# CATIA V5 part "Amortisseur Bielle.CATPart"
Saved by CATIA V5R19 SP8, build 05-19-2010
Part number: Amortisseur Bielle
Bounding box of the stored display mesh (mm): x -7.5 to 57.5, y -30 to 285, z -32.322 to 32.322
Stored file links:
  C:\Users\ThinkMotion\Desktop\EU_thinkMotion\iao\IAO_MMS_Groupe3\yschmidt\Train1434_yschmidt\Train1434_yschmidt\Amortisseur Bielle.CATPart
  C:\Users\ThinkMotion\Desktop\EU_thinkMotion\iao\IAO_MMS_Groupe3\yschmidt\Train1434_yschmidt\Train1434_yschmidt\AssemblageTrainOptimise.CATProduct
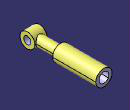
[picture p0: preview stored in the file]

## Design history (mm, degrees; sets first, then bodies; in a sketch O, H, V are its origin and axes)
Set1
  Line1: linked copy from another document
  Plane1: linked copy from another document
Body1 (main body)
  Sketch1 on yz-plane, origin (0, 0, 0), H (0, 1, 0), V (0, 0, 1)
    circle A1 centre (0, 0) radius 30
    reference projected point E1 (0, 0) from Line1
    radius A1 = 30
    concentricity: E1 A1
  Pad1: profile Sketch1, direction (1, 0, 0), length 50
  Sketch2 on zx-plane, origin (0, 0, 0), H (-1, 0, 0), V (0, 0, 1)
    circle A1 centre (-25, 0) radius 20
    point P1 (-25, 0)
    reference projected line E1 (0, -30) -> (0, 30) from edge [start face of Pad1 | face of Pad1 from Sketch1.A1]
    radius A1 = 20
    distance P1 E1 = 25
    coincidence: P1 H
  Pad2: profile Sketch2, direction (0, 1, 0), length 110
  Sketch3 on end face of Pad1, origin (50, 0, 0), H (0, 1, 0), V (0, 0, 1)
    point P1 (0, 0)
    reference projected point E1 (0, 0) from Line1
    coincidence: P1 E1
  Hole1: placed by Sketch3, at (50, 0, 0) direction (-1, 0, 0), diameter 30, through (limit type 6)
  Sketch4 on end face of Pad2, origin (0, 110, 0), H (-1, 0, 0), V (0, 0, 1)
    circle A1 centre (-25, 0) radius 32.5
    point P1 (-25, 0)
    reference projected circle E1 centre (-25, 0) radius 20 from edge [face of Pad2 from Sketch2.A1 | end face of Pad2]
    radius A1 = 32.5
    coincidence: P1 H
    concentricity: A1 E1
  Pad3: profile Sketch4, direction (0, 1, 0), up to Plane1
  Sketch5 on end face of Pad3, origin (25, 285, 0), H (1, 0, 0), V (0, 0, -1)
    point P1 (0, 0)
    reference projected circle E1 centre (0, 0) radius 32.5 from edge [face of Pad3 from Sketch4.A1 | end face of Pad3]
    concentricity: P1 E1
  Hole2: placed by Sketch5, at (25, 285, 0) direction (0, -1, 0), diameter 40, depth 150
